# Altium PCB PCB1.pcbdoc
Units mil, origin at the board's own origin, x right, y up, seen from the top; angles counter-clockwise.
Board outline 3400 x 5045 mil, 2 copper layers (Top Layer, Bottom Layer), stack 62.2 mil thick; 56 components, 40 nets, 192 pads, 34 vias.
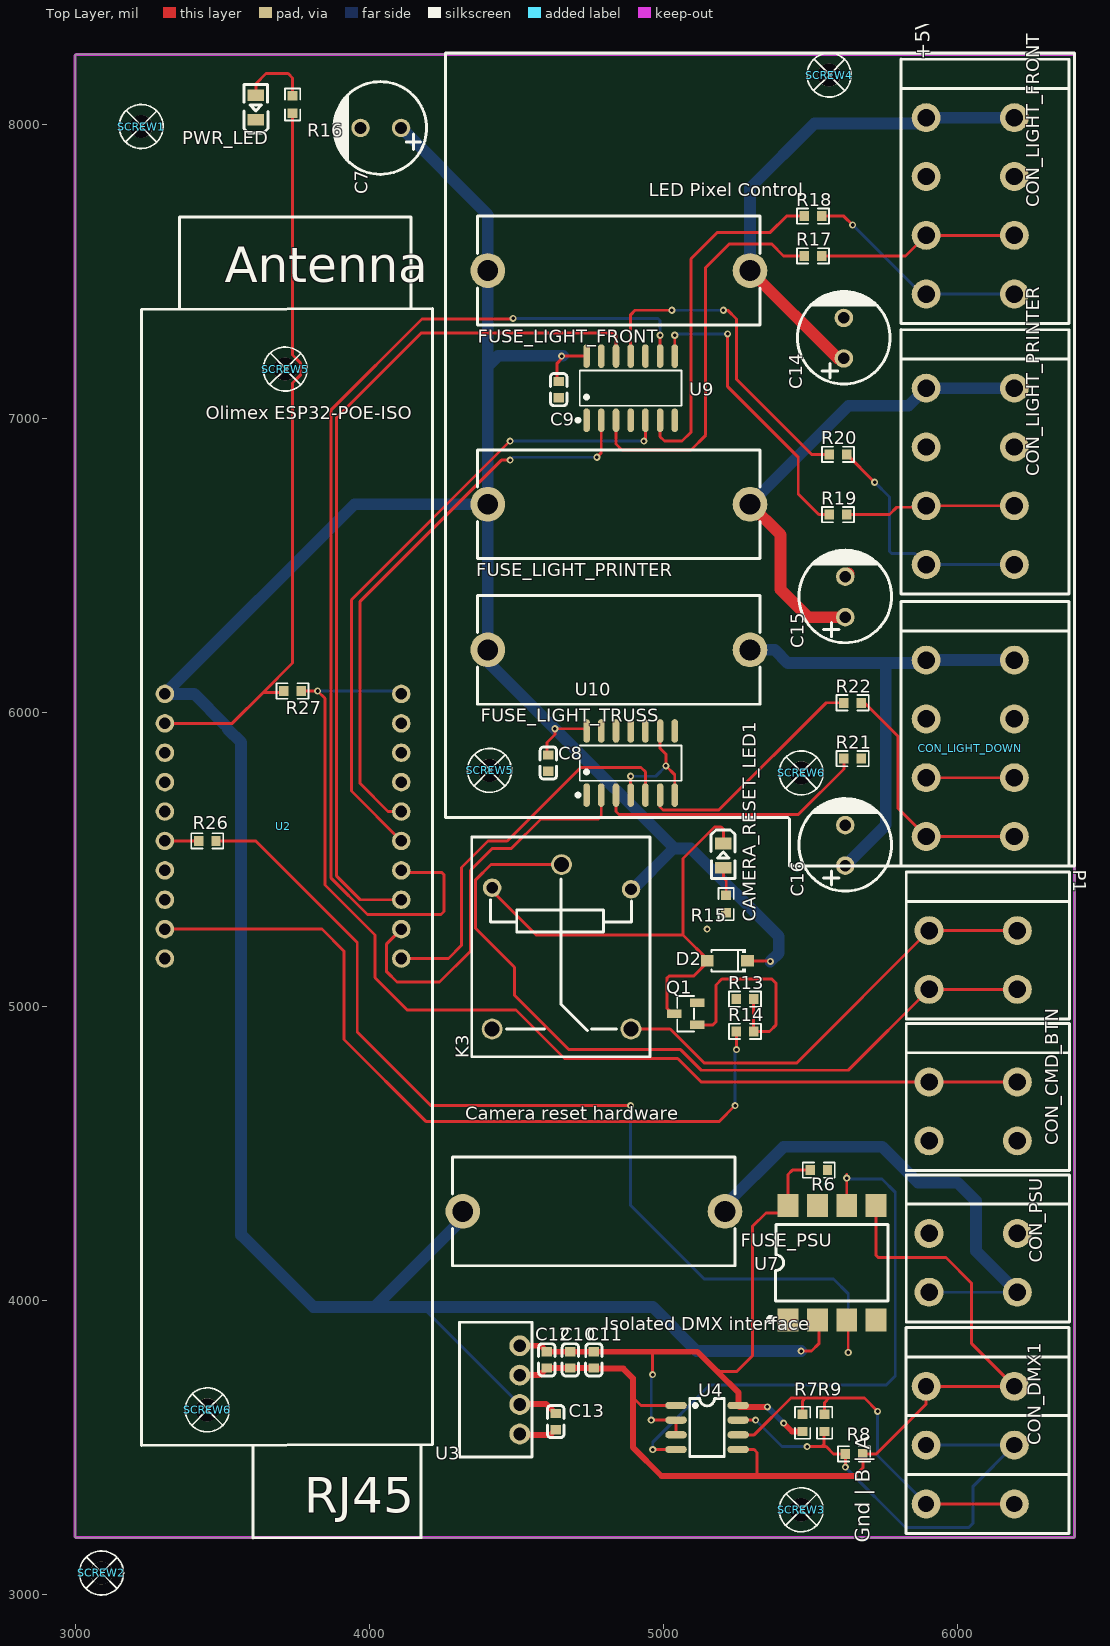
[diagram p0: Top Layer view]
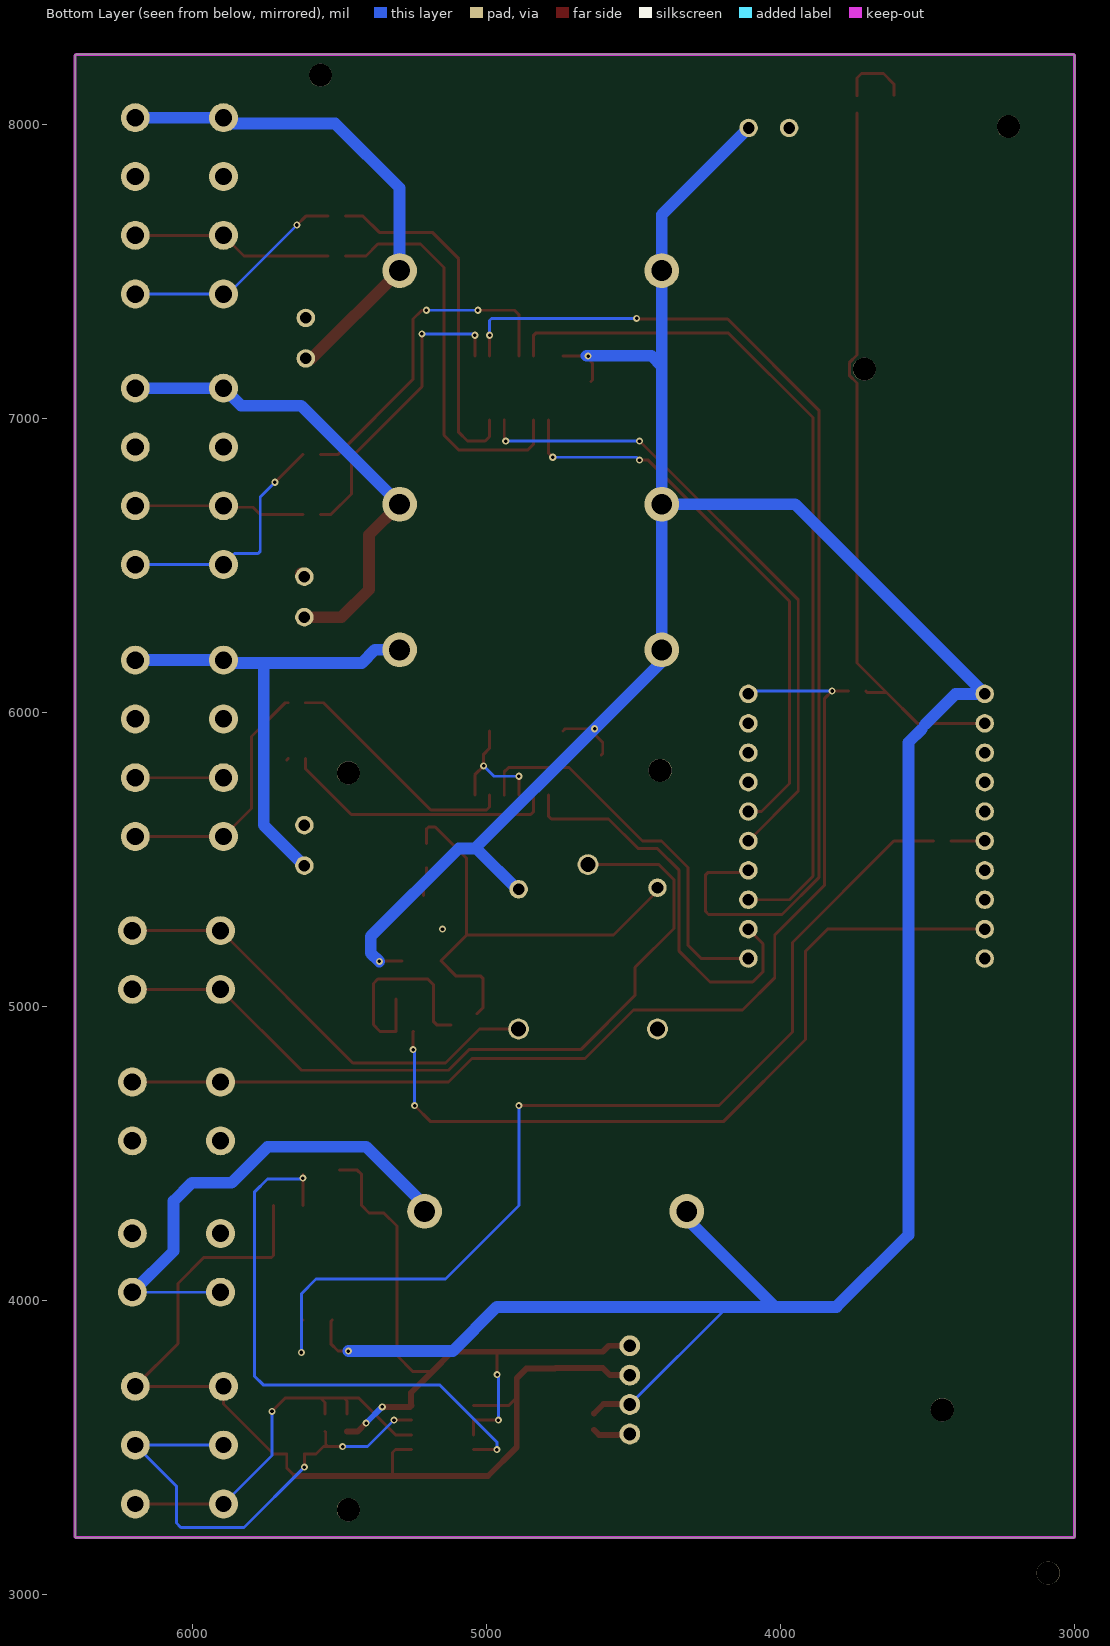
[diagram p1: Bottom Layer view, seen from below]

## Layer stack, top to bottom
Top Solder Mask Layer: solder mask 0.4, Dk 3.3
Top Layer: signal copper 1.4
Dielectric1: surface 59.4, FR4, Dk 4.5
Bottom Layer: signal copper 1.4
Bottom Solder Mask Layer: solder mask 0.4, Dk 3.3

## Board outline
3005,8239.8 ccw(c3005,8234.8) 3000,8234.8 3000,3199.8 ccw(c3005,3199.8) 3005,3194.8 6395,3194.8 ccw(c6395,3199.8) 6400,3199.8 6400,8234.8 ccw(c6395,8234.8) 6395,8239.8

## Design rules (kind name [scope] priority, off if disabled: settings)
BoardOutlineClearance copperThickness1oz [All] p0: genericclearance=10 ignorepadtopadclearanceinfootprint=FALSE except(0: Arc-SplitContinuation Track-SplitContinuation SMDPad-SplitContinuation THPad-SplitContinuation Via-SplitContinuation Fill-SplitContinuation Poly-SplitContinuation Region-SplitContinuation Text-SplitContinuation)
BoardOutlineClearance copperThickness2oz [All] p0: genericclearance=10 ignorepadtopadclearanceinfootprint=FALSE except(0: Arc-SplitContinuation Track-SplitContinuation SMDPad-SplitContinuation THPad-SplitContinuation Via-SplitContinuation Fill-SplitContinuation Poly-SplitContinuation Region-SplitContinuation Text-SplitContinuation)
BoardOutlineClearance Plane_innerPlane [All] p0: genericclearance=10 ignorepadtopadclearanceinfootprint=FALSE except(0: Arc-SplitContinuation Track-SplitContinuation SMDPad-SplitContinuation THPad-SplitContinuation Via-SplitContinuation Fill-SplitContinuation Poly-SplitContinuation Region-SplitContinuation Text-SplitContinuation)
BoardOutlineClearance Copper_copperRegion [All] p0: genericclearance=10 ignorepadtopadclearanceinfootprint=FALSE except(0: Arc-SplitContinuation Track-SplitContinuation SMDPad-SplitContinuation THPad-SplitContinuation Via-SplitContinuation Fill-SplitContinuation Poly-SplitContinuation Region-SplitContinuation Text-SplitContinuation)
BoardOutlineClearance otherClearance [All] p0: genericclearance=10 ignorepadtopadclearanceinfootprint=FALSE except(0: Arc-SplitContinuation Track-SplitContinuation SMDPad-SplitContinuation THPad-SplitContinuation Via-SplitContinuation Fill-SplitContinuation Poly-SplitContinuation Region-SplitContinuation Text-SplitContinuation)
Clearance copperThickness1oz [All] p1: gap=7 ignorepadtopadclearanceinfootprint=FALSE
Clearance copperThickness2oz [All] p1: gap=7 ignorepadtopadclearanceinfootprint=FALSE
Clearance Plane_innerPlane [All] p1: gap=7 ignorepadtopadclearanceinfootprint=FALSE
Clearance Copper_copperRegion [All] p1: gap=7 ignorepadtopadclearanceinfootprint=FALSE
Clearance otherClearance [All] p1: gap=7 ignorepadtopadclearanceinfootprint=FALSE
DiffPairsRouting differentialPair [All] p1: maxuncoupledlength=10 minlimit=6 maxlimit=Infinity mostfreqgap=6 toplayer_minwidth=5 toplayer_prefwidth=10 toplayer_maxwidth=100 bottomlayer_minwidth=5 bottomlayer_prefwidth=10 bottomlayer_maxwidth=100
PasteMaskExpansion pasteMaskExpansion [All] p1: expansion=0
PlaneConnect innerPlane [All] p1: planeconnectstyle=Relief reliefexpansion=20 reliefentries=4 reliefconductorwidth=10 reliefairgap=10
PolygonConnect copperRegion [All] p1: connectstyle=Relief reliefentries=4 reliefconductorwidth=10 polygonreliefangle="90 Angle" airgapwidth=10
RoutingVias viaSize [All] p1: viastyle="Through Hole" holewidth=12.0078 minholewidth=11.811 maxholewidth=248.0314 width=12.0078 minwidth=11.811 maxwidth=248.0314
SolderMaskExpansion solderMaskExpansion [IsVia] p1: useseparateexpansions=TRUE expansion=-1000 expansionbottom=-1000
SolderMaskExpansion solderMaskExpansion [All] p2: useseparateexpansions=TRUE expansion=2 expansionbottom=2
Width copperThickness1oz [All] p1: maxlimit=100 minlimit=5 preferedwidth=10
Width copperThickness2oz [All] p1: maxlimit=100 minlimit=8 preferedwidth=10

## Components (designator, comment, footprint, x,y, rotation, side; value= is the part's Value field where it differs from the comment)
C7 "470uF" CAP-TH_BD8.0-P3.50-D0.5-FD 4040,7989.8 r180 top
C8 "1uF" C0603 4610,5829.8 r270 top
C9 "1uF" C0603 4645,7099.8 r270 top
C10 "100nF" C0603 4685,3799.8 r90 top
C11 "100nF" C0603 4765,3799.8 r90 top
C12 "100nF" C0603 4605,3799.8 r90 top
C13 "4.7uF" C0603 4635,3589.8 r270 top
C14 "470uF" CAP-TH_BD8.0-P3.50-D0.5-FD 5615,7274.8 r90 top
C15 "470uF" CAP-TH_BD8.0-P3.50-D0.5-FD 5620,6394.8 r90 top
C16 "470uF" CAP-TH_BD8.0-P3.50-D0.5-FD 5620,5549.8 r90 top
CAMERA_RESET_LED1 "NCD0805R1" LED0805-R-RD 5205,5514.8 r270 top
CON_CMD_BTN "WJ142R-5.08-02P-14-00A" CONN-TH_2P-P5.08_WJ142R-5.08-2P 6055,4644.8 r270 top
CON_DMX1 "WJ142R-5.08-03P-14-00A" CONN-TH_3P-P5.08_WJ142R-5.08-3P 6045,3509.8 r90 top
CON_LIGHT_DOWN "WJ142R-5.08-04P-14-00A" CONN-TH_WJ142R-5.08-4P 6045,5879.8 r270 top
CON_LIGHT_FRONT "WJ142R-5.08-04P-14-00A" CONN-TH_WJ142R-5.08-4P 6045,7724.8 r270 top
CON_LIGHT_PRINTER "WJ142R-5.08-04P-14-00A" CONN-TH_WJ142R-5.08-4P 6045,6804.8 r270 top
CON_PSU "WJ142R-5.08-02P-14-00A" CONN-TH_2P-P5.08_WJ142R-5.08-2P 6055,4129.8 r270 top
D2 "1N4148W" SOD-123F_L2.7-W1.6-LS3.8-RD 5218.9,5157 r180 top
FUSE_LIGHT_FRONT "PTF-77" FUSE-TH_L24.4-W9.4-P22.60 4850,7504.8 r0 top
FUSE_LIGHT_PRINTER "PTF-77" FUSE-TH_L24.4-W9.4-P22.60 4850,6709.8 r0 top
FUSE_LIGHT_TRUSS "PTF-77" FUSE-TH_L24.4-W9.4-P22.60 4850,6214.8 r0 top
FUSE_PSU "PTF-77" FUSE-TH_L24.4-W9.4-P22.60 4765,4304.8 r180 top
K3 "BRD-SS-105L" RELAY-TH_BRD-SS-1XXL 4655,5204.8 r90 top
P1 "WJ142R-5.08-02P-14-00A" CONN-TH_2P-P5.08_WJ142R-5.08-2P 6055,5159.8 r270 top
PWR_LED "NCD0805R1" LED0805-R-RD 3615,8059.8 r90 top
Q1 "MMBT2222A 1P" SOT-23-3_L2.9-W1.3-P1.90-LS2.4-BR 5077.1,4977 r0 top
R6 "470Ω" R0603#1 5530,4444.8 r0 top
R7 "680Ω" R0603#2 5474.7,3585.7 r270 top
R8 "680Ω" R0603#1 5650,3479.8 r180 top
R9 "120Ω" R0603#3 5549.7,3585.7 r90 top
R13 "10kΩ" R0603#3 5278.9,5027 r0 top
R14 "1kΩ" R0603#3 5278.9,4917 r0 top
R15 "1kΩ" R0603#1 5215,5349.8 r270 top
R16 "1kΩ" R0603#1 3740,8069.8 r270 top
R17 "100Ω" R0603#1 5510,7554.8 r0 top
R18 "100Ω" R0603#1 5510,7689.8 r0 top
R19 "100Ω" R0603#1 5595,6674.8 r0 top
R20 "100Ω" R0603#1 5595,6879.8 r0 top
R21 "100Ω" R0603#1 5645,5844.8 r0 top
R22 "100Ω" R0603#1 5645,6034.8 r0 top
R26 "330Ω" R0603#1 3450,5564.8 r0 top
R27 "10kΩ" R0603#1 3740,6074.8 r180 top
SCREW1 "" Screw-Hole-M2 3225,7994.8 r0 top
SCREW2 "" Screw-Hole-M2 3090,3074.8 r0 top
SCREW3 "" Screw-Hole-M2 5470,3289.8 r0 top
SCREW4 "" Screw-Hole-M2 5565,8169.8 r0 top
SCREW5 "" Screw-Hole-M2 3715,7169.8 r0 top
SCREW5 "" Screw-Hole-M2 4410,5804.8 r0 top
SCREW6 "" Screw-Hole-M2 3450,3629.8 r0 top
SCREW6 "" Screw-Hole-M2 5470,5796.1 r0 top
U2 "ESP32-POE-ISO" COMM-TH_20P-P2.54_ESP32-POE-ISO 3705,5614.8 r0 top
U3 "100kHz" PWRM-TH_B0505S-1W 4512.9,3697.7 r90 top
U4 "MAX3485ESA" SOP-8_L4.9-W3.9-P1.27-LS6.0-BL 5150,3569.8 r270 top
U7 "6N137S" SMT-8_L9.7-W6.6-P2.54-LS10.3-BL 5575,4129.8 r0 top
U9 "SN74AHCT125DR" SOIC-14_L8.7-W3.9-P1.27-LS6.0-BL 4890,7104.8 r0 top
U10 "SN74AHCT125DR" SOIC-14_L8.7-W3.9-P1.27-LS6.0-BL 4890,5829.8 r0 top

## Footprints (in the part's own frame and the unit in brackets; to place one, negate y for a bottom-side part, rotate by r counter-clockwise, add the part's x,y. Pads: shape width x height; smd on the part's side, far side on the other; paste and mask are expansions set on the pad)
C0603 [mil]
  rect 31.5x35.4 smd: 1(-27.6,0) 2(27.6,0)
  silkscreen extent -55,-28 55,28
CAP-TH_BD8.0-P3.50-D0.5-FD [mil]
  round 63 hole 39.4: 1(-68.9,0) 2(68.9,0)
  silkscreen extent -156,-158 159,158
COMM-TH_20P-P2.54_ESP32-POE-ISO [mil]
  round 63 hole 39.4: 1(-399.3,450) 2(-399.3,350) 3(-399.3,250) 4(-399.3,150) 5(-399.3,50) 6(-399.3,-50) 7(-399.3,-150) 8(-399.3,-250) 9(-399.3,-350) 10(-399.3,-450) 11(404.6,-450) 12(404.6,-350) 13(404.6,-250) 14(404.6,-150) 15(404.6,-50) 16(404.6,50) 17(404.6,150) 18(404.6,250) 19(404.6,350) 20(404.6,450)
  silkscreen extent -479,-2421 512,2073
CONN-TH_2P-P5.08_WJ142R-5.08-2P [mil]
  round 98.4 hole 59.1: 1(-100,150) 1(-100,-150) 2(100,150) 2(100,-150)
  silkscreen extent -299,-228 201,328
CONN-TH_3P-P5.08_WJ142R-5.08-3P [mil]
  round 98.4 hole 55.1: 1(200,-150) 1(200,150) 2(0,150) 2(0,-150) 3(-200,-150) 3(-200,150)
  silkscreen extent -300,-336 400,219
CONN-TH_WJ142R-5.08-4P [mil]
  round 98.4 hole 59.1: 1(-300,-150) 1(-300,150) 2(-100,150) 2(-100,-150) 3(100,150) 3(100,-150) 4(300,-150) 4(300,150)
  silkscreen extent -499,-236 400,336
FUSE-TH_L24.4-W9.4-P22.60 [mil]
  round 118.1 hole 70.9: 1(-445.9,0) 2(445.9,0)
  silkscreen extent -480,-185 480,185
LED0805-R-RD [mil]
  rect 39.4x55.1 smd: 1(41.4,0) 2(-41.4,0)
  silkscreen extent -88,-41 78,40
PWRM-TH_B0505S-1W [mil]
  round 70.9 hole 43.3: 1(-150,0) 2(-50,0) 3(50,0) 4(150,0)
  silkscreen extent -228,-41 230,205
R0603#1 [mil]
  rect 31.8x34 smd paste-3937 mask+2: 1(-29.7,0) 2(29.7,0)
  silkscreen extent -54,-26 54,26
R0603#2 [mil]
  rect 31.8x34 smd paste-3937 mask+2: 1(-29.6,0) 2(29.7,0)
  silkscreen extent -55,-26 55,26
R0603#3 [mil]
  rect 31.8x34 smd paste-3937 mask+2: 1(-29.7,0) 2(29.6,0)
  silkscreen extent -54,-26 54,26
RELAY-TH_BRD-SS-1XXL [mil]
  round 70.9 hole 51.2: 1(-279.5,236.2) 2(-279.5,-236.2) 5(279.5,0)
  round 63 hole 39.4: 3(200.8,236.2) 4(195.8,-236.2)
  silkscreen extent -374,-301 374,306
Screw-Hole-M2 [mil]
  round 78.7 hole 78.7: 1(0,0)
  silkscreen extent -75,-75 75,75
SMT-8_L9.7-W6.6-P2.54-LS10.3-BL [mil]
  rect 70.9x78.7 smd: 1(-150,-194.9) 2(-50,-194.9) 3(50,-194.9) 4(150,-194.9) 5(150,194.9) 6(50,194.9) 7(-50,194.9) 8(-150,194.9)
  silkscreen extent -217,-201 191,130
SOD-123F_L2.7-W1.6-LS3.8-RD [mil]
  rect 43.3x39.4 smd: 1(-68.3,0) 2(68.3,0)
  silkscreen extent -63,-40 54,39
SOIC-14_L8.7-W3.9-P1.27-LS6.0-BL [mil]
  oval 22.6x80.2 smd: 1(-150,-109) 2(-100,-109) 3(-50,-109) 4(0,-109) 5(50,-109) 6(100,-109) 7(150,-109) 8(150,109) 9(100,109) 10(50,109) 11(0,109) 12(-50,109) 13(-100,109) 14(-150,109)
  silkscreen extent -185,-115 173,60
SOP-8_L4.9-W3.9-P1.27-LS6.0-BL [mil]
  oval 24.8x73.4 smd: 1(-75,-105.6) 2(-25,-105.6) 3(25,-105.6) 4(75,-105.6) 5(75,105.6) 6(25,105.6) 7(-25,105.6) 8(-75,105.6)
  silkscreen extent -98,-59 98,58
SOT-23-3_L2.9-W1.3-P1.90-LS2.4-BR [mil]
  rect 49.2x27.6 smd: 1(39.4,-37.4) 2(39.4,37.4) 3(-39.4,0)
  silkscreen extent -29,-60 29,60

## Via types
v1: diameter 24, hole 12, Top Layer to Bottom Layer, 34 vias

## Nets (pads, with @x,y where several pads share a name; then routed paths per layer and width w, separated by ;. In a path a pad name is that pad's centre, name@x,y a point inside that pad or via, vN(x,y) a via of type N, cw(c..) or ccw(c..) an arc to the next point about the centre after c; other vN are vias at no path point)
3.3V: R15.2 R16.2 R27.2 U2.2 | length 2483.7
  Top Layer w10: U2.2 3535,5964.8 3640,6069.8 ; R27.2 3705.3,6069.8 3640,6069.8 ; R16.2 3740,7217.3 3766.3,7191 3766.3,7148.6 3740,7122.3 3740,6169.8 3640,6069.8
485/TX: R26.1 U2.6 | length 114.6
  Top Layer w10: U2.6 R26.1
$1N7133: PWR_LED.1 R16.1 | length 244.6
  Top Layer w10: PWR_LED.1 3615,8139.8 3650,8174.8 3725,8174.8 3740,8159.8 R16.1
$1N7729: CON_LIGHT_FRONT.3 R17.2 | length 684.3
  Top Layer w10: R17.2 5825,7554.8 5895,7624.8 CON_LIGHT_FRONT.3@6195,7624.8
$1N7768: CON_LIGHT_FRONT.4 R18.2 | length 765.1
  Top Layer w10: R18.2 5615,7689.8 v1(5645,7659.8)
  Bottom Layer w10: v1(5645,7659.8) 5880,7424.8 5895,7424.8 CON_LIGHT_FRONT.4@6195,7424.8
$1N8516: R18.1 U9.6 | length 1215
  Top Layer w10: U9.6 4990,6939.8 5005,6924.8 5065,6924.8 5095,6954.8 5095,7544.8 5185,7634.8 5365,7634.8 5420,7689.8 R18.1
$1N8525: R19.1 U9.8 | length 1031.8
  Top Layer w10: U9.8 v1(5040,7284.8) ; v1(5220,7289.8) 5220,7109.8 5460,6869.8 5460,6744.8 5530,6674.8 R19.1
  Bottom Layer w10: v1(5040,7284.8) 5045,7289.8 v1(5220,7289.8)
$1N8531: R20.1 U9.11 | length 1145.6
  Top Layer w10: U9.11 4890,7354.8 4905,7369.8 v1(5030,7369.8) ; v1(5205,7369.8) 5220,7369.8 5250,7339.8 5250,7134.8 5505,6879.8 R20.1
  Bottom Layer w10: v1(5030,7369.8) v1(5205,7369.8)
$1N8539: R17.1 U9.3 | length 1370
  Top Layer w10: U9.3 4840,6914.8 4860,6894.8 5095,6894.8 5145,6944.8 5145,7514.8 5225,7594.8 5370,7594.8 5410,7554.8 R17.1
$1N8578: R21.1 U10.3 | length 934.6
  Top Layer w10: U10.3 4840,5664.8 4850,5654.8 5460.3,5654.8 5615.3,5809.8 R21.1
$1N8587: R22.1 U10.6 | length 821.7
  Top Layer w10: U10.6 4990,5679.8 5000.1,5669.7 5189.9,5669.7 5555,6034.8 R22.1
$1N8748: CON_LIGHT_PRINTER.4 R20.2 | length 834
  Top Layer w10: R20.2 5719.7,6784.8 v1(5720,6784.8)
  Bottom Layer w10: v1(5720,6784.8) 5770,6734.8 5770,6549.8 5777.1,6542.7 5857.1,6542.7 5895,6504.8 CON_LIGHT_PRINTER.4@6195,6504.8
$1N8751: CON_LIGHT_PRINTER.3 R19.2 | length 582.7
  Top Layer w10: R19.2 5770,6674.8 5795,6699.8 5890,6699.8 5895,6704.8 CON_LIGHT_PRINTER.3@6195,6704.8
$1N9030: CON_LIGHT_DOWN.3 R21.2 | length 307.1
  Top Layer w10: R21.2 R21.2@5679.7,5839.8 ; CON_LIGHT_DOWN.3@5895,5779.8 CON_LIGHT_DOWN.3@6195,5779.8
$1N9032: CON_LIGHT_DOWN.4 R22.2 | length 852.3
  Top Layer w10: R22.2 5685,6034.8 5800,5919.8 5800,5674.8 5895,5579.8 CON_LIGHT_DOWN.4@6195,5579.8
$1N23327: CON_PSU.2 FUSE_PSU.1 | length 1702.1
  Bottom Layer w10: CON_PSU.2@5905,4029.8 CON_PSU.2@6205,4029.8
  Bottom Layer w40: FUSE_PSU.1 5210.9,4325.7 5410,4524.8 5745,4524.8 5867.5,4402.3 6002.5,4402.3 6065,4339.8 6065,4169.8 CON_PSU.2@6205,4029.8
$2N1101: R6.2 U4.4 U7.6 | length 1938.4
  Top Layer w10: v1(4965,3494.8) U4.4 ; U7.6 5625,4429.8
  Bottom Layer w10: v1(4965,3494.8) 4965,3519.8 5160,3714.8 5760,3714.8 5790,3744.8 5790,4369.8 5745,4414.8 5630,4414.8 v1@5625,4419.8
  other v1: 5625,4417.8
$2N1167: R26.2 U7.3 | length 3478.2
  Top Layer w10: R26.2 3615,5564.8 3960,5219.8 3960,4914.8 4210,4664.8 v1(4890,4664.8) ; U7.3 5630,3929.9 v1(5630,3824.8)
  Bottom Layer w10: v1(4890,4664.8) 4890,4324.8 5140,4074.8 5580,4074.8 5630,4024.8 v1(5630,3824.8)
$2N7403: K3.2 P1.1 | length 1548
  Top Layer w10: K3.2 5024.5,4925.3 5140,4809.8 5455,4809.8 5905,5259.8 P1.1@6205,5259.8
$2N7405: K3.5 P1.2 | length 2690.6
  Top Layer w10: K3.5 4414.5,5484.3 4362.9,5432.7 4362.9,5266.9 4495,5134.8 4495,5039.8 4680,4854.8 5060,4854.8 5130,4784.8 5630,4784.8 5905,5059.8 P1.2@6205,5059.8
$2N7407: CAMERA_RESET_LED1.2 D2.2 K3.3 Q1.3 | length 1624.4
  Top Layer w10: K3.3@4418.8,5394.8 4568.7,5244.8 5067.7,5244.8 ; Q1.3@5032.4,4977 5012.9,4996.5 5012.9,5097.7 5020,5104.8 5103.3,5104.8 5155.5,5157 5067.7,5244.8 ; CAMERA_RESET_LED1.2@5205,5556.1 5205,5604.8 5197.9,5611.9 5175,5611.9 5067.7,5504.6 5067.7,5244.8
$2N7408: CAMERA_RESET_LED1.1 R15.1 | length 98.1
  Top Layer w10: CAMERA_RESET_LED1.1@5205,5473.5 5205,5439.8 5215,5429.8 R15.1
$2N7412: Q1.1 R13.2 R14.2 | length 742.9
  Top Layer w10: Q1.1@5121.8,4939.4 5169.6,4939.4 5180,4949.8 5180,5074.8 5200,5094.8 5370,5094.8 5385,5079.8 5385,4939.8 5362.2,4917 R14.2 R13.2
+5V: C7.1 C8.1 C9.1 C13.1 D2.1 FUSE_LIGHT_FRONT.1 FUSE_LIGHT_PRINTER.1 FUSE_LIGHT_TRUSS.1 FUSE_PSU.2 K3.4 U2.1 U3.2 U7.2 U9.14 U10.14 | length 10990
  Top Layer w10: C8.1 4605,5862.4 4605,5899.8 4632.3,5927.1 v1(4632.3,5946.4) 4732.4,5946.4 U10.14 ; C9.1 4640,7132.4 4640,7189.8 4655,7204.8 v1(4655,7213.8) U9.14 ; D2.1 5362.8,5157 v1(5365,5154.8) ; v1(5470,3829.8) 5505.3,3829.8 5530,3854.5 5530,3929.9 U7.2
  Top Layer w20: U3.2 4515,3649.8 4602.6,3649.8 C13.1
  Bottom Layer w10: 4180.8,3979.8 U3.2
  Bottom Layer w40: 3510,5959.8 3405,6064.8 U2.1 3950.7,6709.8 FUSE_LIGHT_PRINTER.1 ; 3520,5944.8 3565,5899.8 3565,4224.8 3810,3979.8 4019.2,3979.8 ; C7.1 4404.1,7694.6 FUSE_LIGHT_FRONT.1 4404.1,7179.8 ; FUSE_PSU.2 4319.1,4279.7 4019.2,3979.8 ; v1@4660,7214.8 4439.1,7214.8 4404.1,7179.8 ; K3.4@4891.2,5394.8 5035.6,5539.1 5039.6,5539.1 ; v1(5365,5154.8) 5393.7,5183.5 5393.7,5240 5094.6,5539.1 5039.6,5539.1 ; v1(5470,3829.8) 5115,3829.8 4965,3979.8 4180.8,3979.8 4019.2,3979.8 ; FUSE_LIGHT_PRINTER.1 4404.1,6174.6 v1(4632.3,5946.4) 5039.6,5539.1 ; FUSE_LIGHT_PRINTER.1 4404.1,7179.8
  other v1: 5150,5264.8
CAMERA_RESET_RELAY: R14.1 U2.9 | length 2663.7
  Top Layer w10: U2.9 3840,5264.8 3915,5189.8 3915,4889.8 4195,4609.8 5190,4609.8 v1(5245,4664.8) ; R14.1 5250,4916.2 v1(5250,4854.8)
  Bottom Layer w10: v1(5245,4664.8) 5245,4849.8 v1(5250,4854.8)
CMD_BTN: CON_CMD_BTN.1 R27.1 U2.20 | length 3731.9
  Top Layer w10: R27.1 v1(3825,6074.8) 3850,6049.8 3850,5414.8 4020,5244.8 4020,5099.8 4130,4989.8 4500,4989.8 4665,4824.8 5050,4824.8 5130,4744.8 5905,4744.8 CON_CMD_BTN.1@6205,4744.8
  Bottom Layer w10: v1(3825,6074.8) 4099.6,6074.8 U2.20
DMX-A: CON_DMX1.3 R7.1 R9.2 U4.6 | length 1347.8
  Top Layer w10: U4.6 5310,3544.8 5435,3669.8 5485,3669.8 ; R7.1 5475,3615.6 5475,3659.8 5485,3669.8 ; R9.2 5550,3615.6 5550,3654.8 5565,3669.8 ; v1(5730,3624.8) 5685,3669.8 5565,3669.8 ; CON_DMX1.3@5895,3309.8 CON_DMX1.3@6195,3309.8 ; 5485,3669.8 5565,3669.8
  Bottom Layer w10: v1(5730,3624.8) 5730,3474.8 CON_DMX1.3@5895,3309.8
DMX-B: CON_DMX1.2 R8.2 R9.1 U4.7 | length 1661.8
  Top Layer w10: U4.7 v1(5315,3594.8) ; v1(5490,3504.8) 5540,3504.8 ; R9.1 5547.1,3553.4 5547.1,3511.9 5540,3504.8 ; v1(5620,3434.8) 5620,3479.5 R8.2 5580,3479.8 5555,3504.8 5540,3504.8
  Bottom Layer w10: v1(5315,3594.8) 5405,3504.8 v1(5490,3504.8) ; v1(5620,3434.8) 5825,3229.8 6040,3229.8 6055,3244.8 6055,3369.8 6195,3509.8 CON_DMX1.2@5895,3509.8
DMX-GND: C10.1 C11.1 C12.1 CON_DMX1.1 R8.1 U3.3 U4.1 U4.5 U7.5 | length 3423.6
  Top Layer w10: 4897.5,3672 4924.7,3644.8 U4.1 ; U4.5 5310,3494.8 5320,3484.8 5320,3407.4 5317.4,3404.8 ; 5652.4,3404.8 5679.7,3432.1 R8.1 5725,3479.8 5895,3649.8 5895,3709.8 6195,3709.8 6050,3854.8 6050,4059.8 5962.1,4147.7 5732.1,4147.7 5725,4154.8 U7.5
  Top Layer w20: U3.3 4580.5,3747.7 C12.1 C10.1 C11.1 4767.4,3769.8 4865,3769.8 4897.5,3737.3 4897.5,3672 4897.5,3502.3 4995,3404.8 5317.4,3404.8 5652.4,3404.8
DMX-VCC: C10.2 C11.2 C12.2 R6.1 R7.2 U3.4 U4.2 U4.3 U4.8 U7.8 | length 2397.5
  Top Layer w10: v1(4960,3594.8) U4.2 U4.3 ; v1(4964.6,3749.4) 4964.6,3827.1 4964.8,3827.4 ; 5185.1,3759.7 5250.1,3759.7 5305,3814.5 5305,4254.8 5349.9,4299.7 5400,4299.7 U7.8 5425,4430.1 5439.7,4444.8 R6.1
  Top Layer w20: U3.4 4584.7,3847.7 C12.2 C10.2 C11.2 4964.8,3827.4 5117.4,3827.4 5185.1,3759.7 5257.1,3687.7 5257.1,3646.3 U4.8 5260.6,3639.8 v1(5355,3639.8) ; v1(5410,3584.8) 5438.8,3556 R7.2
  Bottom Layer w10: v1(4960,3594.8) 4960,3744.8 v1(4964.6,3749.4)
  Bottom Layer w20: v1(5355,3639.8) v1(5410,3584.8)
GND: C7.2 C8.2 C9.2 C13.2 C14.2 C15.2 C16.2 CON_CMD_BTN.2 CON_LIGHT_DOWN.2 CON_LIGHT_FRONT.2 CON_LIGHT_PRINTER.2 CON_PSU.1 PWR_LED.2 Q1.2 R13.1 U2.3 U3.1 U9.1 U9.4 U9.7 U9.10 U9.13 U10.1 U10.4 U10.7 U10.9 U10.10 U10.12 U10.13 | length 583.4
  Top Layer w10: U10.4 v1(4890,5784.8) ; U10.9 4990,5879.8 5010,5859.8 v1(5010,5819.8) 5040,5789.8 U10.7
  Top Layer w20: U3.1 4515.8,3544.8 4617.6,3544.8 C13.2
  Top Layer w40: C15.2 C15.2@5631.1,6474.8
  Bottom Layer w10: v1(4890,5784.8) 4975,5784.8 v1(5010,5819.8)
LIGHT_FRONT_CLK: U2.15 U9.5 | length 2182
  Top Layer w10: U2.15 3940,5734.4 3940,6384.8 v1(4480,6924.8) ; v1(4935,6924.8) 4940,6929.8 U9.5
  Bottom Layer w10: v1(4480,6924.8) v1(4935,6924.8)
LIGHT_FRONT_DATA: U2.16 U9.2 | length 1939.1
  Top Layer w10: U2.16 4065,5664.8 3970,5759.8 3970,6379.8 4450,6859.8 v1(4480,6859.8) ; v1(4775,6869.8) 4790,6884.8 U9.2
  Bottom Layer w10: v1(4480,6859.8) 4490,6869.8 v1(4775,6869.8)
LIGHT_PRINTER_CLK: U2.13 U9.12 | length 2955.6
  Top Layer w10: U2.13 3970,5364.8 3890,5444.8 3890,7004.8 4177.1,7291.9 4832.9,7291.9 4840,7284.8 U9.12
LIGHT_PRINTER_DATA: U2.14 U9.9 | length 3680.7
  Top Layer w10: U2.14 4117.6,5456.9 4247.9,5456.9 4255,5449.8 4255,5324.8 4245,5314.8 3995,5314.8 3870,5439.8 3870,7029.8 4180,7339.8 4487.9,7339.8 v1(4490,7341.9) ; U9.9 v1(4990,7284.8)
  Bottom Layer w10: v1(4490,7341.9) 4982.9,7341.9 4990,7334.8 v1(4990,7284.8)
LIGHT_TRUSS_CLK: U2.11 U10.5 | length 1340.1
  Top Layer w10: U2.11 4270,5164.8 4315,5209.8 4315,5474.8 4405,5564.8 4470,5564.8 4720,5814.8 4925,5814.8 4940,5799.8 U10.5
LIGHT_TRUSS_DATA: U2.12 U10.2 | length 1376.2
  Top Layer w10: U2.12 4109.6,5264.4 4060,5214.8 4060,5119.8 4095,5084.8 4240,5084.8 4345,5189.8 4345,5464.8 4420,5539.8 4485,5539.8 4585,5639.8 4780,5639.8 4790,5649.8 U10.2
PSU_LIGHT1: C14.1 CON_LIGHT_FRONT.1 FUSE_LIGHT_FRONT.2 | length 1721.9
  Top Layer w40: FUSE_LIGHT_FRONT.2 5594.8,7205.9 C14.1
  Bottom Layer w40: FUSE_LIGHT_FRONT.2 5295.9,7785.7 5515,8004.8 5875,8004.8 5895,8024.8 CON_LIGHT_FRONT.1@6195,8024.8
PSU_LIGHT2: C15.1 CON_LIGHT_PRINTER.1 FUSE_LIGHT_PRINTER.2 | length 1654.7
  Top Layer w40: FUSE_LIGHT_PRINTER.2 5400,6605.7 5400,6419.8 5493.9,6325.9 C15.1
  Bottom Layer w40: FUSE_LIGHT_PRINTER.2 5630.9,7044.8 5835,7044.8 5895,7104.8 CON_LIGHT_PRINTER.1@6195,7104.8
PSU_LIGHT3: C16.1 CON_LIGHT_DOWN.1 FUSE_LIGHT_TRUSS.2 | length 1667.9
  Bottom Layer w40: FUSE_LIGHT_TRUSS.2 5380,6214.8 5425,6169.8 5758,6169.8 ; C16.1 5758,5618.9 5758,6169.8 ; CON_LIGHT_DOWN.1@6195,6179.8 5895,6179.8 5885,6169.8 5758,6169.8
pads on no net: K3.1 SCREW1.1 SCREW2.1 SCREW3.1 SCREW4.1 SCREW5.1 SCREW6.1 U2.4 U2.5 U2.7 U2.8 U2.10 U2.17 U2.18 U2.19 U7.1 U7.4 U7.7 U10.8 U10.11

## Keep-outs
Board Outline Layer:
  the board outline again, w10

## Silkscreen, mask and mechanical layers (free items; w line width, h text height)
Top Silkscreen Layer:
  lines w10: 4260,5644.8 5425,5644.8 5430,5639.8 5430,5479.8 6400,5479.8 6400,8244.8 4260,8244.8 4260,5644.8
  text "+5V | Gnd | D | Clk" at 5907.5,8222.3 h50 r90
  text "LED Pixel Control" at 4951.5,7757.3 h45
  text "Antenna" at 3510,7464.8 h120
  text "Olimex ESP32-POE-ISO" at 3445,6999.8 h45
  text "+5V | Gnd | D | Clk" at 6987.5,5807.3 h50 r90
  text "+5V | Gnd | D | Clk" at 8252.5,5057.3 h50 r90
  text "In | Out" at 7227.5,4929.8 h50 r90
  text "Camera reset hardware" at 4327.1,4617.3 h45
  text "+5V | Gnd" at 8257.5,3912.3 h50 r90
  text "Isolated DMX interface" at 4800,3899.8 h45
  text "RJ45" at 3780,3279.8 h120
  text "Gnd | B | A" at 5702.5,3177.3 h50 r90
